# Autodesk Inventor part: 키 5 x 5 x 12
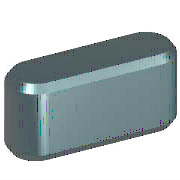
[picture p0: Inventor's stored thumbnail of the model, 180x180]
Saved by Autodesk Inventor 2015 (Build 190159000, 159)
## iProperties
Created: 2012-02
Part Number: 키 5 x 5 x 12
Material: 강철, 연강
Description: 키 및 해당 키홈
Document SubType Name: Modeling
Standard: KS B 1311
Designer: mduedu
Standards Organization: KS
Language: ko-KR
Size Designation: 5 x 5 x 12
Categories: <MemberInstance><Categories><Category DisplayName="샤프트 부품" InternalName="7f7aeb1f-a693-4053-b835-cee3144e0d98" Mnemonic="SHFT"><Category DisplayName="키" Interna
Density: 1 g/cm^3
Appearance: 노란색
IsCustomPart: 1
Author: mduedu
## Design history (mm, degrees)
workplane "Work Plane1"
workplane "Work Plane2"
sketch "스케치1"
  geometry: L1 (2.5, 2.5)-(9.5, 2.5); L2 (9.5, -2.5)-(2.5, -2.5); L3 (0, 9.4)-(0, -7.4) reference; L4 (-5, 0)-(30, 0) reference; L5 (12, 0)-(12, 7); A1 r 2.5 centre (2.5, 0) between (2.5, 2.5) and (2.5, -2.5); A2 r 2.5 centre (9.5, 0) between (9.5, -2.5) and (9.5, 2.5)
  constraints: 6 end point, 5 point on circle, 4 tangent, 3 point on line, 2 centre point, 1 horizontal, 1 parallel, 1 perpendicular
  dimensions: "d0" = 2.5 radius of A1 (= 0.5 x PB); "d13" = 2.5 radius of A2 (= 0.5 x PB); "d14" = 12 distance between parallel lines of L5 L3 (= NLG)
extrude "본체1" new body sketch "스케치1" taper "d3" = 0 deg; stored distance "d4" = 10
workplane "Work Plane3"
body "Solid1"
chamfer "모따기1" distance "d8" = 0.4 (= PHH); stored, may be unused: second distance "d9" = 0.4 (= PHH), angle "d15" = 45 deg
other parameters: "d1" = -3 (= -PNT), "d2" = 2 (= PH - PNT), "NLG" = 12 [user parameter; used in 3 equation terms], "PB" = 5 [user parameter; used in 2 equation terms], "PNT" = 3 [user parameter; used in 2 equation terms], "PH" = 5 [user parameter; used in 1 equation term], "PHH" = 0.4 [user parameter; used in 2 equation terms], "d10" = 0, "d16" = 0, "d17" = 0, "d18" = 0, "WDMIN" = 12 [user parameter], "PLB2" = 12 (= NLG) [user parameter], "WDMAX" = 17 [user parameter], "PLB1" = 12 (= NLG) [user parameter], "RR" = 0.16 [user parameter], "PUEB" = 2.3 [user parameter]
